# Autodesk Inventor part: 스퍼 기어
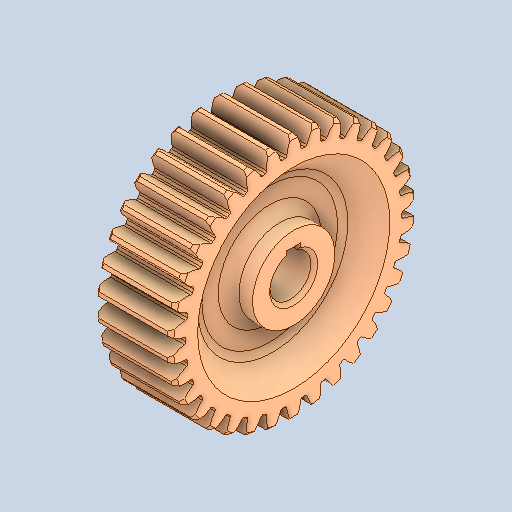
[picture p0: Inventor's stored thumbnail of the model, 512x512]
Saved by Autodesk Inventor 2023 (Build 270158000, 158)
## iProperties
Created: 2026-03
Part Number: 스퍼 기어
Material: 강철, 합금
Document SubType Name: Modeling
Designer: 4강의실
Density: 7.73 g/cm^3
Appearance: 기본값
Author: jhkim
Sending System: Autodesk Inventor 2026
Preprocessor: ST-DEVELOPER v20.1
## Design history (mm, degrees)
feature "솔리드1"
node "솔리드2"
